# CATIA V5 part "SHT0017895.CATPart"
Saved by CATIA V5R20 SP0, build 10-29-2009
Part number: SHT0017895
Bounding box of the stored display mesh (mm): x -453 to 31, y 0 to 645.5, z 0.9 to 30.9
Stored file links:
  F:\福田A6\17-新能源车\数据\变更后数据\A668100000147（SHT0017898）-副司机座椅底支架总成\SHT0017895-副驾底支架左下板\SHT0017895.CATPart

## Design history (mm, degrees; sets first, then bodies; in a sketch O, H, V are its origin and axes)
Body1 (main body)
Body2
  Solid1: solid without history
  Sketch1 on face of Solid1, origin (0, 0, 0.9), H (1, 0, 0), V (0, -1, 0)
